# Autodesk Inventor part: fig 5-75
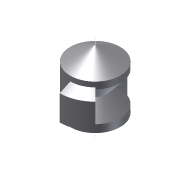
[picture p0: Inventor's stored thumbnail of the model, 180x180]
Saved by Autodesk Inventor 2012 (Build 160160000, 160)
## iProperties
Created: 2004-05
Part Number: fig 5-75
Document SubType Name: Modeling
Designer: CADCIM Technologies
Manufacturer: Standard
Standards Organization: Custom
Density: 1 g/cm^3
Material: Default
Author: CADCIM Technologies
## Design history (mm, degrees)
sketch "Sketch1"
  geometry: L1 (0, -21.51)-(0, 21.51); L2 (0, 21.51)-(-14.639, 13.059); L3 (-14.639, 13.059)-(-14.639, -13.059); L4 (-14.639, -13.059)-(0, -21.51); 2 further points
  constraints: 8 end point, 1 coincident, 1 equal length, 1 midpoint, 1 parallel, 1 vertical, 1 other
  dimensions: "d3" = 120 deg angle of L4 L3
revolve "Revolution1" sketch "Sketch1" stored, may be unused: angle "d0" = 90 deg
workaxis "Work Axis1"
sketch "Sketch2"
  geometry: L1 (-15.658, 10.423)-(-7.144, 0); L2 (-7.144, 0)-(-15.658, -9.738); L3 (-15.658, -9.738)-(-15.658, 10.423); L4 (0, -25.812)-(0, 34.416) reference
  constraints: 6 end point, 1 vertical
revolve "Revolution2" sketch "Sketch2" stored, may be unused: angle "d4" = 140 deg
sketch "Sketch3"
  geometry: L1 (-14.955, 9.983)-(-20.736, 7.191); L2 (-20.736, 7.191)-(-20.736, -7.686); L3 (-20.736, -7.686)-(-15, -10.57); L4 (0, -25.812)-(0, 34.416) reference
  constraints: 6 end point, 1 equal length, 1 vertical
revolve "Revolution4" sketch "Sketch3" stored, may be unused: angle "d9" = 45 deg
body "Solid1"
other parameters: "d11" = 45 deg
